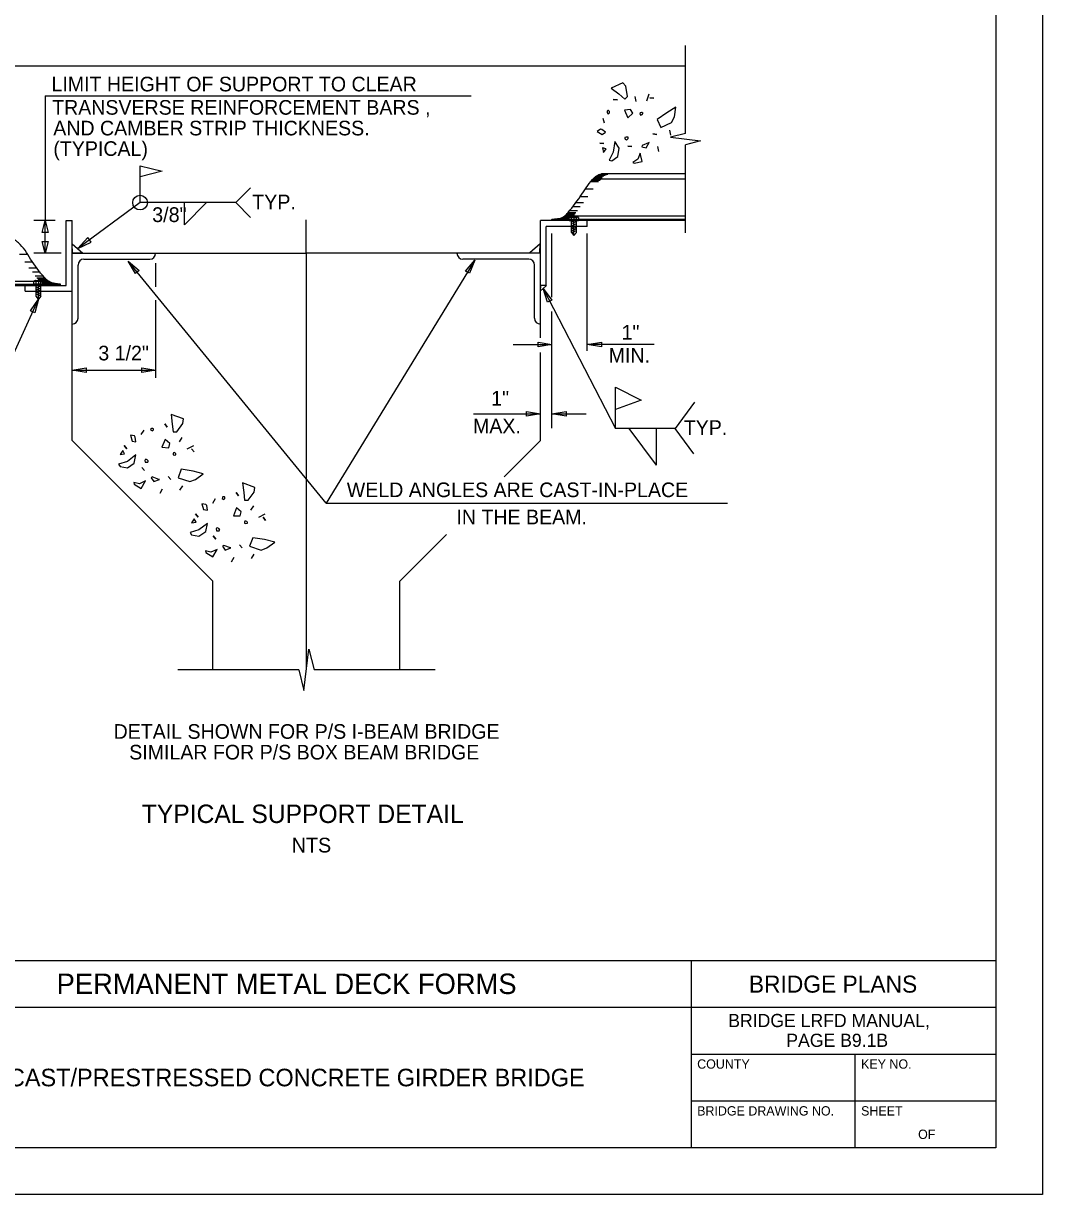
# Model space of a CAD drawing. Extents: x 0 to 34, y 0 to 23.5.
# Drawn here: x 23.12 to 34, y 0 to 12.5 of the extents above; entities that cross this region are included whole.
import ezdxf

# ---------------------------------------------------------------- set-up
doc = ezdxf.new("R2010")
doc.units = 0
for name, color, linetype in [('BORDER_ANNO_Cutsheet', 7, 'Continuous'), ('BRDG_ANNO_Anno-Sheet', 7, 'Continuous'), ('BRDG_ANNO_General-Notes', 7, 'Continuous'), ('BRDG_BASE_Dtlctrln', 7, 'Continuous'), ('BRDG_BASE_Obj-Line', 7, 'Continuous'), ('BRDG_BASE_Pattern', 7, 'Continuous'), ('Default', 7, 'Continuous')]:
    doc.layers.add(name, color=color, linetype=linetype)

# ---------------------------------------------------------------- blocks, each defined once
blk = doc.blocks.new('TERM')
at = {"layer": 'Default'}
for p, q in [((-1.6, -0.3), (-1.6, 0.3)), ((-1.6, 0.3), (0, 0)), ((0, 0), (-1.6, -0.3))]:
    blk.add_line(p, q, dxfattribs=at)

msp = doc.modelspace()

# ---------------------------------------------------------------- linework, layer by layer
at = {"layer": 'BORDER_ANNO_Cutsheet'}
msp.add_lwpolyline([(0, 22), (34, 22), (34, 0), (0, 0)], close=True, dxfattribs=at)
at = {"layer": 'BRDG_ANNO_Anno-Sheet'}
for p, q in [((19.25, 2.5), (33.5, 2.5)), ((30.25, 0.5), (30.25, 2.5)), ((22.25, 2), (30.25, 2)), ((30.25, 2), (33.5, 2)), ((30.25, 1.5), (33.5, 1.5)), ((32, 0.5), (32, 1.5)), ((30.25, 1), (33.5, 1))]:
    msp.add_line(p, q, dxfattribs=at)
msp.add_lwpolyline([(1.5, 21.5), (33.5, 21.5), (33.5, 0.5), (1.5, 0.5)], close=True, dxfattribs=at)
at = {"layer": 'BRDG_ANNO_General-Notes'}
for p, q in [((23.35, 11.73), (27.9, 11.73)), ((23.35, 11.73), (23.35, 10.399)), ((24.364, 10.59), (24.364, 10.984)), ((25.386, 10.59), (25.543, 10.748)), ((24.364, 10.59), (23.698, 10.099)), ((25.386, 10.59), (24.364, 10.59)), ((25.073, 10.59), (24.837, 10.354)), ((24.837, 10.354), (24.837, 10.59)), ((25.386, 10.59), (25.543, 10.433)), ((23.458, 10.399), (23.231, 10.399)), ((23.35, 10.049), (23.35, 10.399)), ((28.762, 9.582), (28.762, 10.259)), ((29.139, 9.009), (29.139, 10.259)), ((23.807, 10.217), (23.698, 10.099)), ((23.698, 10.099), (23.843, 10.169)), ((23.843, 10.169), (23.807, 10.217)), ((23.522, 10.049), (23.231, 10.049)), ((26.351, 7.38), (24.238, 9.966)), ((24.314, 9.833), (24.238, 9.966)), ((24.238, 9.966), (24.353, 9.865)), ((24.531, 9.693), (24.531, 9.944)), ((27.938, 9.975), (26.351, 7.38)), ((27.84, 9.86), (27.938, 9.975)), ((27.938, 9.975), (27.881, 9.836)), ((24.353, 9.865), (24.314, 9.833)), ((27.881, 9.836), (27.84, 9.86)), ((28.667, 9.673), (29.439, 8.179)), ((28.713, 9.528), (28.667, 9.673)), ((28.667, 9.673), (28.76, 9.55)), ((22.976, 8.893), (23.281, 9.56)), ((23.195, 9.434), (23.281, 9.56)), ((23.281, 9.56), (23.241, 9.412)), ((24.531, 8.721), (24.531, 9.55)), ((28.76, 9.55), (28.713, 9.528)), ((23.241, 9.412), (23.195, 9.434)), ((28.762, 8.182), (28.762, 9.429)), ((28.347, 9.075), (28.762, 9.075)), ((28.614, 9.05), (28.614, 9.1)), ((28.614, 9.1), (28.762, 9.075)), ((28.762, 9.075), (28.614, 9.05)), ((29.139, 9.075), (29.289, 9.1)), ((29.852, 9.075), (29.139, 9.075)), ((29.289, 9.05), (29.139, 9.075)), ((29.289, 9.1), (29.289, 9.05)), ((23.64, 8.802), (23.79, 8.827)), ((23.64, 8.802), (24.531, 8.802)), ((23.79, 8.778), (23.64, 8.802)), ((23.79, 8.827), (23.79, 8.778)), ((24.381, 8.778), (24.381, 8.827)), ((24.381, 8.827), (24.531, 8.802)), ((24.531, 8.802), (24.381, 8.778)), ((29.439, 8.179), (29.439, 8.62)), ((30.285, 8.46), (30.076, 8.179)), ((27.924, 8.335), (28.639, 8.335)), ((28.489, 8.31), (28.489, 8.36)), ((28.489, 8.36), (28.639, 8.335)), ((28.639, 8.335), (28.489, 8.31)), ((28.762, 8.335), (28.913, 8.36)), ((28.762, 8.335), (29.126, 8.335)), ((28.913, 8.31), (28.762, 8.335)), ((28.913, 8.36), (28.913, 8.31)), ((30.076, 8.179), (29.439, 8.179)), ((29.879, 7.786), (29.587, 8.179)), ((29.879, 7.786), (29.879, 8.179)), ((30.278, 7.909), (30.076, 8.179)), ((26.351, 7.38), (30.637, 7.38))]:
    msp.add_line(p, q, dxfattribs=at)
for points in [[(24.364, 10.984), (24.6, 10.925), (24.364, 10.866)], [(23.64, 10.151), (23.751, 10.052), (23.643, 10.052)], [(28.634, 10.151), (28.524, 10.054), (28.632, 10.054)], [(28.637, 9.646), (28.703, 9.705), (28.639, 9.705)], [(29.439, 8.62), (29.715, 8.48), (29.439, 8.381)]]:
    msp.add_lwpolyline(points, close=True, dxfattribs=at)
msp.add_circle((24.364, 10.591), 0.0787, dxfattribs=at)
at = {"layer": 'BRDG_BASE_Dtlctrln'}
for p, q in [((26.139, 10.049), (26.139, 10.406)), ((28.996, 10.463), (28.996, 10.397)), ((28.996, 10.239), (28.996, 10.397)), ((26.139, 10.049), (26.139, 5.601)), ((23.281, 9.784), (23.281, 9.718)), ((23.281, 9.56), (23.281, 9.718))]:
    msp.add_line(p, q, dxfattribs=at)
at = {"layer": 'BRDG_BASE_Obj-Line'}
for p, q in [((30.189, 11.329), (30.189, 12.268)), ((22.258, 12.05), (26.139, 12.05)), ((26.139, 12.05), (30.189, 12.05)), ((30.189, 11.329), (30.029, 11.289)), ((30.029, 11.289), (30.348, 11.25)), ((30.348, 11.25), (30.189, 11.209)), ((30.189, 10.269), (30.189, 11.209)), ((29.331, 10.879), (29.247, 10.879)), ((29.343, 10.886), (29.259, 10.886)), ((29.357, 10.891), (29.274, 10.891)), ((30.189, 10.898), (29.291, 10.898)), ((29.257, 10.812), (29.173, 10.812)), ((29.272, 10.827), (29.19, 10.827)), ((29.282, 10.832), (29.198, 10.832)), ((30.189, 10.841), (29.2, 10.841)), ((29.289, 10.846), (29.205, 10.846)), ((29.298, 10.856), (29.215, 10.856)), ((29.303, 10.864), (29.223, 10.864)), ((29.316, 10.874), (29.232, 10.874)), ((29.144, 10.652), (29.062, 10.652)), ((29.2, 10.733), (29.116, 10.733)), ((29.062, 10.544), (28.981, 10.544)), ((29.1, 10.588), (29.016, 10.588)), ((23.576, 9.705), (23.576, 10.399)), ((23.576, 10.399), (23.64, 10.399)), ((23.64, 10.111), (23.64, 10.399)), ((28.639, 10.111), (28.639, 10.399)), ((29.139, 10.399), (28.639, 10.399)), ((30.189, 10.411), (28.762, 10.411)), ((28.762, 10.399), (28.762, 10.411)), ((30.189, 10.399), (28.762, 10.399)), ((28.919, 10.418), (28.836, 10.418)), ((28.944, 10.426), (28.86, 10.426)), ((28.959, 10.433), (28.875, 10.433)), ((28.972, 10.438), (28.888, 10.438)), ((30.189, 10.446), (28.898, 10.446)), ((28.988, 10.451), (28.908, 10.451)), ((28.996, 10.456), (28.913, 10.456)), ((28.998, 10.463), (28.918, 10.463)), ((29.008, 10.472), (28.924, 10.472)), ((29.018, 10.48), (28.934, 10.48)), ((28.947, 10.402), (28.947, 10.431)), ((29.033, 10.502), (28.949, 10.502)), ((28.949, 10.399), (29.045, 10.399)), ((28.959, 10.436), (29.036, 10.436)), ((28.972, 10.399), (28.972, 10.431)), ((28.972, 10.271), (28.972, 10.399)), ((28.972, 10.367), (29.021, 10.387)), ((28.974, 10.387), (29.003, 10.399)), ((29.023, 10.399), (29.023, 10.431)), ((29.023, 10.271), (29.023, 10.399)), ((29.047, 10.402), (29.047, 10.431)), ((29.139, 10.335), (29.139, 10.399)), ((28.701, 9.705), (28.701, 10.335)), ((29.139, 10.335), (28.701, 10.335)), ((28.972, 10.344), (29.023, 10.367)), ((28.972, 10.31), (29.023, 10.33)), ((28.972, 10.29), (29.023, 10.313)), ((28.972, 10.271), (29.023, 10.293)), ((28.972, 10.271), (28.996, 10.239)), ((28.974, 10.325), (29.023, 10.347)), ((28.996, 10.239), (29.023, 10.271)), ((23.077, 10.039), (23.161, 10.039)), ((23.64, 10.049), (23.64, 10.111)), ((28.639, 10.049), (28.639, 10.111)), ((23.133, 9.959), (23.217, 9.959)), ((23.177, 9.895), (23.261, 9.895)), ((23.702, 9.355), (23.702, 9.924)), ((23.763, 9.985), (24.467, 9.985)), ((28.514, 9.985), (27.81, 9.985)), ((28.575, 9.355), (28.575, 9.924)), ((23.215, 9.85), (23.298, 9.85)), ((23.244, 9.808), (23.328, 9.808)), ((23.318, 9.757), (23.244, 9.757)), ((23.261, 9.788), (23.343, 9.788)), ((23.269, 9.779), (23.353, 9.779)), ((23.279, 9.769), (23.362, 9.769)), ((23.284, 9.762), (23.367, 9.762)), ((23.289, 9.757), (23.372, 9.757)), ((22.258, 9.752), (23.382, 9.752)), ((22.258, 9.718), (23.515, 9.718)), ((22.258, 9.705), (23.515, 9.705)), ((23.138, 9.705), (23.576, 9.705)), ((23.138, 9.644), (23.138, 9.705)), ((23.138, 9.644), (23.64, 9.644)), ((23.231, 9.723), (23.231, 9.752)), ((23.328, 9.72), (23.234, 9.72)), ((23.305, 9.649), (23.254, 9.668)), ((23.256, 9.72), (23.256, 9.752)), ((23.256, 9.592), (23.256, 9.72)), ((23.305, 9.688), (23.256, 9.708)), ((23.305, 9.665), (23.256, 9.688)), ((23.305, 9.631), (23.256, 9.651)), ((23.305, 9.611), (23.256, 9.634)), ((23.305, 9.708), (23.276, 9.72)), ((23.305, 9.72), (23.305, 9.752)), ((23.305, 9.744), (23.389, 9.744)), ((23.305, 9.592), (23.305, 9.72)), ((23.318, 9.739), (23.402, 9.739)), ((23.33, 9.723), (23.33, 9.752)), ((23.335, 9.732), (23.417, 9.732)), ((23.357, 9.727), (23.441, 9.727)), ((23.515, 9.705), (23.515, 9.718)), ((28.701, 9.705), (28.639, 9.705)), ((23.305, 9.592), (23.256, 9.614)), ((23.281, 9.56), (23.256, 9.592)), ((23.305, 9.592), (23.281, 9.56)), ((23.64, 9.294), (23.64, 9.294)), ((26.112, 5.381), (26.167, 5.822)), ((26.167, 5.822), (26.222, 5.601)), ((26.059, 5.601), (24.766, 5.601)), ((26.059, 5.601), (26.112, 5.381)), ((27.515, 5.601), (26.222, 5.601))]:
    msp.add_line(p, q, dxfattribs=at)
for points in [[(25.139, 5.601), (25.139, 6.549), (23.64, 8.05), (23.64, 10.049), (26.139, 10.049)], [(28.639, 9.147), (28.639, 10.049), (26.139, 10.049)], [(28.253, 7.663), (28.639, 8.05), (28.639, 8.989)], [(27.138, 5.601), (27.138, 6.549), (27.635, 7.046)]]:
    msp.add_lwpolyline(points, dxfattribs=at)
for centre, radius, start, end in [((28.959, 10.417), 0.0198, 50.7833, 129.2167), ((28.949, 10.401), 0.0025, 180, 270), ((28.997, 10.367), 0.0695, 68.9268, 111.0732), ((29.034, 10.417), 0.0198, 50.7833, 129.2167), ((29.044, 10.401), 0.0025, 270, 360), ((24.467, 10.049), 0.0625, 270, 360), ((27.81, 10.049), 0.0625, 180, 270), ((23.764, 9.924), 0.0625, 90, 180), ((28.513, 9.924), 0.0625, 0, 90), ((23.243, 9.738), 0.0198, 50.7833, 129.2167), ((23.28, 9.688), 0.0695, 68.9268, 111.0732), ((23.318, 9.738), 0.0198, 50.7833, 129.2167), ((23.233, 9.722), 0.0025, 180, 270), ((23.328, 9.722), 0.0025, 270, 0), ((23.639, 9.356), 0.0625, 270, 360), ((28.638, 9.356), 0.0625, 180, 270)]:
    msp.add_arc(centre, radius, start, end, dxfattribs=at)
for points in [[(28.762, 10.411), (28.804, 10.418), (28.836, 10.421), (28.888, 10.441), (28.934, 10.485), (29.082, 10.682), (29.144, 10.772), (29.213, 10.856), (29.247, 10.881), (29.291, 10.898)], [(23.515, 9.718), (23.473, 9.724), (23.441, 9.729), (23.392, 9.747), (23.343, 9.791), (23.195, 9.988), (23.136, 10.082), (23.064, 10.162), (23.033, 10.187), (22.985, 10.205)]]:
    msp.add_spline(points, degree=3, dxfattribs=at)
at = {"layer": 'BRDG_BASE_Pattern'}
for p, q in [((29.662, 11.671), (29.651, 11.725)), ((29.774, 11.678), (29.798, 11.75)), ((29.321, 11.437), (29.308, 11.489)), ((30.032, 11.309), (30.02, 11.363)), ((29.904, 11.137), (29.892, 11.189)), ((24.376, 8.114), (24.406, 8.16)), ((24.784, 8.037), (24.814, 8.084)), ((24.868, 7.963), (24.937, 7.997)), ((24.578, 7.489), (24.604, 7.535)), ((24.789, 7.52), (24.819, 7.567)), ((25.141, 7.382), (25.168, 7.43)), ((25.547, 7.307), (25.577, 7.353)), ((25.631, 7.233), (25.7, 7.267)), ((25.34, 6.757), (25.37, 6.805)), ((25.552, 6.79), (25.581, 6.836))]:
    msp.add_line(p, q, dxfattribs=at)
for points in [[(29.476, 11.75), (29.539, 11.696), (29.569, 11.725), (29.549, 11.833), (29.52, 11.87), (29.392, 11.814)], [(29.461, 11.688), (29.416, 11.693)], [(29.849, 11.705), (29.805, 11.71)], [(29.357, 11.54), (29.375, 11.548), (29.375, 11.563), (29.367, 11.573), (29.36, 11.573), (29.352, 11.565), (29.351, 11.56), (29.351, 11.553)], [(29.572, 11.496), (29.626, 11.545), (29.601, 11.584), (29.537, 11.579)], [(29.724, 11.53), (29.734, 11.545), (29.729, 11.55), (29.724, 11.553), (29.717, 11.553), (29.705, 11.55), (29.7, 11.54), (29.705, 11.533), (29.705, 11.528), (29.71, 11.523)], [(29.923, 11.391), (30.039, 11.447), (30.069, 11.506), (30.084, 11.609), (29.987, 11.55), (29.884, 11.476)], [(29.298, 11.317), (29.333, 11.341), (29.293, 11.371), (29.279, 11.376), (29.244, 11.351)], [(29.559, 11.258), (29.577, 11.274), (29.574, 11.289), (29.569, 11.289), (29.554, 11.289), (29.539, 11.284), (29.539, 11.277), (29.542, 11.269), (29.544, 11.268), (29.549, 11.263)], [(29.882, 11.319), (29.838, 11.324)], [(29.316, 11.22), (29.272, 11.225)], [(29.311, 11.127), (29.341, 11.166), (29.301, 11.176)], [(29.4, 11.036), (29.466, 11.081), (29.48, 11.171), (29.434, 11.243), (29.416, 11.13), (29.372, 11.043)], [(29.613, 11.189), (29.572, 11.194)], [(29.769, 11.174), (29.798, 11.233), (29.793, 11.228), (29.724, 11.201), (29.72, 11.186)], [(29.641, 11.012), (29.726, 11.028), (29.705, 11.12), (29.677, 11.053), (29.626, 11.019)], [(24.708, 8.224), (24.716, 8.143), (24.757, 8.143), (24.819, 8.232), (24.826, 8.281), (24.696, 8.327)], [(24.476, 8.163), (24.496, 8.153), (24.506, 8.163), (24.506, 8.175), (24.501, 8.179), (24.491, 8.179), (24.486, 8.179), (24.479, 8.175)], [(24.654, 8.192), (24.627, 8.227)], [(24.278, 8.045), (24.317, 8.037), (24.312, 8.086), (24.304, 8.099), (24.263, 8.106)], [(24.597, 7.978), (24.671, 7.973), (24.681, 8.02), (24.632, 8.061)], [(24.15, 7.774), (24.228, 7.759), (24.302, 7.81), (24.319, 7.897), (24.228, 7.828), (24.135, 7.799)], [(24.152, 7.902), (24.199, 7.909), (24.179, 7.943)], [(24.221, 7.963), (24.194, 7.997)], [(24.73, 7.894), (24.747, 7.899), (24.747, 7.904), (24.745, 7.912), (24.74, 7.917), (24.73, 7.922), (24.72, 7.919), (24.717, 7.912), (24.716, 7.907), (24.716, 7.899)], [(24.942, 7.929), (24.914, 7.963)], [(24.41, 7.73), (24.383, 7.764)], [(24.417, 7.818), (24.445, 7.818), (24.452, 7.83), (24.45, 7.833), (24.44, 7.843), (24.425, 7.85), (24.417, 7.845), (24.415, 7.838), (24.415, 7.835), (24.417, 7.828)], [(24.509, 7.612), (24.57, 7.633), (24.563, 7.633), (24.494, 7.661), (24.481, 7.653)], [(24.691, 7.633), (24.663, 7.668)], [(24.77, 7.653), (24.895, 7.612), (24.957, 7.633), (25.037, 7.695), (24.929, 7.722), (24.804, 7.744)], [(24.302, 7.584), (24.376, 7.538), (24.422, 7.619), (24.358, 7.589), (24.297, 7.602)], [(25.47, 7.494), (25.478, 7.412), (25.519, 7.412), (25.581, 7.5), (25.588, 7.55), (25.458, 7.597)], [(25.239, 7.432), (25.259, 7.422), (25.269, 7.432), (25.269, 7.444), (25.264, 7.451), (25.254, 7.451), (25.249, 7.449), (25.244, 7.444)], [(25.416, 7.461), (25.39, 7.496)], [(24.983, 7.233), (24.957, 7.267)], [(25.04, 7.313), (25.082, 7.307), (25.075, 7.356), (25.067, 7.368), (25.025, 7.375)], [(25.36, 7.248), (25.434, 7.245), (25.444, 7.289), (25.395, 7.331)], [(24.912, 7.043), (24.991, 7.028), (25.067, 7.08), (25.085, 7.166), (24.991, 7.097), (24.898, 7.067)], [(24.914, 7.171), (24.962, 7.179), (24.942, 7.213)], [(25.493, 7.164), (25.51, 7.169), (25.51, 7.174), (25.508, 7.181), (25.503, 7.186), (25.493, 7.19), (25.483, 7.188), (25.48, 7.181), (25.478, 7.176), (25.478, 7.169)], [(25.704, 7.198), (25.677, 7.233)], [(25.173, 6.999), (25.146, 7.033)], [(25.18, 7.087), (25.208, 7.087), (25.214, 7.1), (25.212, 7.102), (25.203, 7.112), (25.188, 7.12), (25.18, 7.115), (25.178, 7.107), (25.178, 7.105), (25.18, 7.097)], [(25.532, 6.923), (25.657, 6.88), (25.719, 6.903), (25.803, 6.964), (25.692, 6.992), (25.567, 7.013)], [(25.067, 6.854), (25.139, 6.807), (25.188, 6.888), (25.121, 6.859), (25.062, 6.871)], [(25.272, 6.88), (25.332, 6.903), (25.328, 6.903), (25.259, 6.93), (25.244, 6.923)], [(25.454, 6.903), (25.426, 6.938)]]:
    msp.add_lwpolyline(points, close=True, dxfattribs=at)

# ---------------------------------------------------------------- block references
at = {"layer": 'BRDG_ANNO_General-Notes', "xscale": 0.07872656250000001, "yscale": 0.11070922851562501}
for p, rotation in [((23.35, 10.399), 90), ((23.35, 10.049), -90)]:
    msp.add_blockref('TERM', p, dxfattribs=dict(at, rotation=rotation))

# ---------------------------------------------------------------- texts
at = {"layer": 'BRDG_ANNO_Anno-Sheet'}
for s, height, p in [('PERMANENT METAL DECK FORMS', 0.21813, (23.473, 2.141)), ('BRIDGE PLANS', 0.18187, (30.864, 2.156)), ('BRIDGE LRFD MANUAL,', 0.14062, (30.644, 1.788)), ('PAGE B9.1B', 0.1406, (31.264, 1.577)), ('COUNTY', 0.0994, (30.312, 1.344)), ('KEY NO.', 0.0994, (32.062, 1.344)), ('PRECAST/PRESTRESSED CONCRETE GIRDER BRIDGE', 0.1875, (22.437, 1.156)), ('BRIDGE DRAWING NO.', 0.09937, (30.312, 0.844)), ('SHEET', 0.0994, (32.062, 0.844)), ('OF', 0.0994, (32.671, 0.594))]:
    msp.add_text(s, height=height, dxfattribs=at).set_placement(p)
at = {"layer": 'BRDG_ANNO_General-Notes'}
for s, height, p in [('LIMIT HEIGHT OF SUPPORT TO CLEAR', 0.15622, (23.418, 11.778)), ('TRANSVERSE REINFORCEMENT BARS ,', 0.15622, (23.425, 11.529)), ('AND CAMBER STRIP THICKNESS.', 0.15622, (23.437, 11.308)), ('(TYPICAL)', 0.1562, (23.438, 11.089)), ('TYP.', 0.1575, (25.56, 10.518)), ('3/8"', 0.1575, (24.493, 10.383)), ('1"', 0.1565, (29.505, 9.127)), ('3 1/2"', 0.1565, (23.918, 8.906)), ('MIN.', 0.1562, (29.367, 8.883)), ('1"', 0.1565, (28.113, 8.424)), ('MAX.', 0.1562, (27.919, 8.128)), ('TYP.', 0.1562, (30.169, 8.111)), ('WELD ANGLES ARE CAST-IN-PLACE', 0.15622, (26.571, 7.446)), ('IN THE BEAM.', 0.15622, (27.742, 7.156)), ('DETAIL SHOWN FOR P/S I-BEAM BRIDGE', 0.15622, (24.081, 4.866)), ('SIMILAR FOR P/S BOX BEAM BRIDGE', 0.15622, (24.248, 4.645)), ('TYPICAL SUPPORT DETAIL', 0.19681, (24.382, 3.967)), ('NTS', 0.1575, (25.983, 3.652))]:
    msp.add_text(s, height=height, dxfattribs=at).set_placement(p)

doc.saveas('drawing.dxf')
